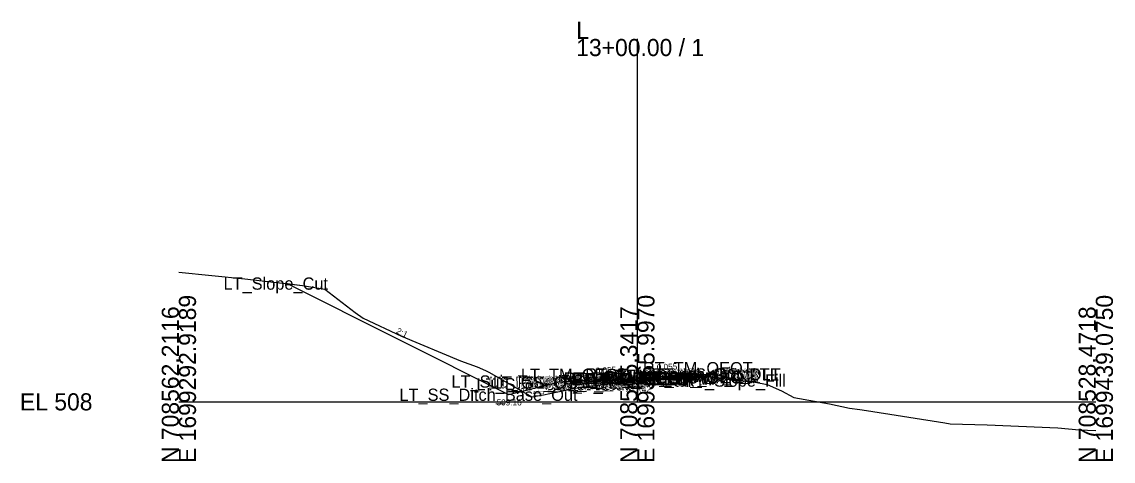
# Model space of a CAD drawing. Extents: x -63 to 1153, y -24 to 9522.
# Drawn here: x -25.7 to 152.8, y 2990.3 to 3062.1 of the extents above; entities that cross this region are included whole.
import ezdxf

# ---------------------------------------------------------------- set-up
doc = ezdxf.new("R2010")
doc.units = 0
for name, color, linetype in [('Default', 7, 'Continuous'), ('Exist Cross Section Cell', 7, 'Continuous'), ('Exist XS Center Line Elevation Label', 7, 'Continuous'), ('Exist XS Ground Line', 7, 'Continuous'), ('Prop CMT DNC', 7, 'Continuous'), ('Prop CMT Pvmt Course 1', 7, 'Continuous'), ('Prop CMT Pvmt Course 2', 7, 'Continuous'), ('Prop CMT Pvmt Surface', 7, 'Continuous'), ('Prop CMT Pvmt Surface Overlay', 7, 'Continuous'), ('Prop CMT Pvmt Surface Shoulder', 7, 'Continuous'), ('Prop CMT Shld Paved Course 1', 7, 'Continuous'), ('Prop CMT Shld Paved Course 2', 7, 'Continuous'), ('Prop CMT Slope Grass', 7, 'Continuous'), ('Prop CMT Subgrade Earthwork', 7, 'Continuous'), ('Prop XS Ditch Standard Text', 7, 'Continuous'), ('Prop XS Earthwork Shape', 7, 'Continuous'), ('Prop XS EOT Tick Mark', 7, 'Continuous'), ('Prop XS SE Text', 7, 'Continuous'), ('Prop XS Side Slope Text', 7, 'Continuous')]:
    doc.layers.add(name, color=color, linetype=linetype)

msp = doc.modelspace()

# ---------------------------------------------------------------- linework, layer by layer
at = {"layer": 'Exist Cross Section Cell'}
for p, q in [((75, 3000), (75, 3059.31)), ((0, 3000), (75, 3000)), ((75, 3000), (150, 3000))]:
    msp.add_line(p, q, dxfattribs=at)
at = {"layer": 'Exist XS Ground Line'}
msp.add_lwpolyline([(0, 3021.18), (10.8, 3020.12), (20.2, 3019.04), (23.85, 3018.4), (28.85, 3014.6), (30.17, 3013.65), (36.4, 3010.71), (46.07, 3006.73), (48.77, 3005.72), (50.17, 3005.1), (50.79, 3004.78), (57.73, 3000.83), (59.65, 3001.15), (60.69, 3001.36), (64.88, 3002.23), (65.63, 3002.38), (74.46, 3003.36), (75, 3003.42), (75.52, 3003.48), (84.57, 3004.15), (85.48, 3004.23), (86.59, 3004.13), (88.81, 3003.84), (94.26, 3003.22), (96.26, 3002.84), (98.58, 3001.79), (100.59, 3000.72), (106.43, 2999.65), (109.71, 2998.96), (111.4, 2998.73), (112.49, 2998.6), (125.28, 2996.55), (126.2, 2996.42), (132.2, 2996.22), (143.78, 2995.76), (147.25, 2995.45), (150, 2995.32)], dxfattribs=at)
at = {"layer": 'Prop CMT Pvmt Course 1'}
for points in [[(75, 3003.95), (65, 3003.4)], [(65, 3003.15), (75, 3003.7)], [(65, 3003.4), (65, 3003.15)], [(75, 3003.95), (85, 3004.5)], [(85, 3004.25), (75, 3003.7)], [(75, 3003.82), (75, 3003.95)], [(75, 3003.82), (75, 3003.95)], [(75, 3003.7), (75, 3003.82), (75, 3003.82)], [(75, 3003.7), (75, 3003.82), (75, 3003.82)], [(85, 3004.5), (85, 3004.25)]]:
    msp.add_lwpolyline(points, dxfattribs=at)
at = {"layer": 'Prop CMT Pvmt Course 2'}
for points in [[(75, 3003.7), (65, 3003.15)], [(65, 3002.9), (75, 3003.45)], [(65, 3003.15), (65, 3002.9)], [(75, 3003.7), (85, 3004.25)], [(85, 3004), (75, 3003.45)], [(75, 3003.45), (75, 3003.7)], [(75, 3003.45), (75, 3003.7)], [(85, 3004.25), (85, 3004)]]:
    msp.add_lwpolyline(points, dxfattribs=at)
at = {"layer": 'Prop CMT Pvmt Surface'}
for points in [[(75, 3003.95), (65, 3003.4)], [(75, 3003.95), (85, 3004.5)]]:
    msp.add_lwpolyline(points, dxfattribs=at)
at = {"layer": 'Prop CMT Pvmt Surface Overlay'}
for points in [[(75, 3003.95), (65, 3003.4)], [(75, 3003.95), (85, 3004.5)]]:
    msp.add_lwpolyline(points, dxfattribs=at)
at = {"layer": 'Prop CMT Pvmt Surface Shoulder'}
for points in [[(65, 3003.4), (64.99, 3003.4)], [(85, 3004.5), (85.01, 3004.5)]]:
    msp.add_lwpolyline(points, dxfattribs=at)
at = {"layer": 'Prop CMT Shld Paved Course 1'}
for points in [[(65, 3003.4), (64.99, 3003.4), (64.73, 3003.13)], [(64.73, 3003.13), (65, 3003.15)], [(65, 3003.15), (65, 3003.4)], [(85, 3004.5), (85.01, 3004.5), (85.25, 3004.26)], [(85, 3004.25), (85, 3004.5)], [(85.25, 3004.26), (85, 3004.25)]]:
    msp.add_lwpolyline(points, dxfattribs=at)
at = {"layer": 'Prop CMT Shld Paved Course 2'}
for points in [[(64.73, 3003.13), (64.46, 3002.87)], [(65, 3003.15), (64.73, 3003.13)], [(64.73, 3003.13), (64.73, 3003.13)], [(65, 3002.9), (65, 3003.15)], [(85, 3004.25), (85.25, 3004.26)], [(85, 3004), (85, 3004.25)], [(85.48, 3004.03), (85, 3004)], [(85.25, 3004.26), (85.25, 3004.26)], [(85.25, 3004.26), (85.48, 3004.03)], [(64.46, 3002.87), (65, 3002.9)]]:
    msp.add_lwpolyline(points, dxfattribs=at)
at = {"layer": 'Prop CMT Slope Grass'}
for points in [[(62, 3003.16), (54, 3001.16), (17.66, 3019.33)], [(64.99, 3003.4), (62, 3003.16)], [(85.01, 3004.5), (88, 3004.48)], [(88, 3004.48), (92.02, 3003.48)]]:
    msp.add_lwpolyline(points, dxfattribs=at)
at = {"layer": 'Prop CMT Subgrade Earthwork'}
for points in [[(64.46, 3002.87), (64.01, 3003.32)], [(75, 3003.45), (65, 3002.9)], [(75, 3003.45), (85, 3004)], [(85, 3004), (85.48, 3004.03)], [(85.48, 3004.03), (85.95, 3004.49)], [(65, 3002.9), (64.46, 3002.87)]]:
    msp.add_lwpolyline(points, dxfattribs=at)
at = {"layer": 'Prop XS Earthwork Shape'}
for points in [[(50.17, 3005.1), (50.79, 3004.78), (56.19, 3001.71), (54, 3001.16), (17.66, 3019.33), (20.2, 3019.04), (23.85, 3018.4), (28.85, 3014.6), (30.17, 3013.65), (36.4, 3010.71), (46.07, 3006.73), (48.77, 3005.72)], [(57.73, 3000.83), (59.65, 3001.15), (60.69, 3001.36), (64.88, 3002.23), (65.63, 3002.38), (74.46, 3003.36), (75, 3003.42), (75.49, 3003.48), (75, 3003.45), (65, 3002.9), (64.46, 3002.87), (64.01, 3003.32), (62, 3003.16), (56.19, 3001.71)], [(85.48, 3004.03), (85.67, 3004.21), (85.48, 3004.23), (84.57, 3004.15), (75.52, 3003.48), (75.49, 3003.48), (85, 3004)], [(85.95, 3004.49), (88, 3004.48), (92.02, 3003.48), (88.81, 3003.84), (86.59, 3004.13), (85.67, 3004.21)]]:
    msp.add_lwpolyline(points, close=True, dxfattribs=at)
at = {"layer": 'Prop XS EOT Tick Mark'}
for points in [[(85, 3004.5), (85, 3005.5)], [(65, 3003.4), (65, 3004.4)]]:
    msp.add_lwpolyline(points, dxfattribs=at)

# ---------------------------------------------------------------- texts
at = {"layer": 'Default'}
msp.add_text('-', height=0.0001, dxfattribs=at).set_placement((0, 3000))
at = {"layer": 'Exist Cross Section Cell'}
for s, p in [('L', (65, 3059.31)), ('13+00.00 / 1', (65, 3056.51)), ('EL 508', (-26, 2998.6))]:
    msp.add_text(s, height=2.8, dxfattribs=at).set_placement(p)
for s, p in [('E 1699292.9189', (2.8, 2990)), ('E 1699365.9970', (77.8, 2990)), ('E 1699439.0750', (152.8, 2990)), ('N 708562.2116', (0, 2990)), ('N 708545.3417', (75, 2990)), ('N 708528.4718', (150, 2990))]:
    msp.add_text(s, height=2.8, rotation=90, dxfattribs=at).set_placement(p)
at = {"layer": 'Exist XS Center Line Elevation Label'}
msp.add_text('511.42', height=1, dxfattribs=at).set_placement((73.13, 3001.56))
at = {"layer": 'Prop CMT DNC'}
for s, p in [('LT_Slope_Cut', (7.3, 3018.33)), ('RT_TM_OEOT', (75.9, 3004.5)), ('LT_TM_OEOT', (55.94, 3003.4)), ('RT_PV1_OEEOP_W', (62.94, 3002.82)), ('LT_PV1_OEEOP_W', (62.98, 3002.82)), ('RT_PV2_OEEOP', (64.26, 3002.7)), ('LT_PV2_OEEOP', (64.31, 3002.7)), ('RT_Sub_Trench_Out_DLT', (66.47, 3003.49)), ('PV1_PGL_W', (67.58, 3002.82)), ('PV1_PGL', (69.47, 3002.95)), ('RT_Sub_Trench_Out', (69.64, 3003.03)), ('RT_PS2_Shelf_Out', (71.18, 3003.26)), ('RT_Sub_OEOT', (75.03, 3003)), ('RT_PV2_OEOT', (75.13, 3003.25)), ('RT_PS2_OEOP', (75.44, 3003.26)), ('RT_PV1_OEOT', (75.69, 3003.5)), ('RT_PS1_OEOP', (75.77, 3003.5)), ('RT_GS_OS_CTL', (77.32, 3003.48)), ('LT_Sub_Trench_Out_DLT', (44.58, 3002.32)), ('LT_Sub_Trench_Out', (48.67, 3001.87)), ('LT_PS2_Shelf_Out', (50.71, 3002.13)), ('LT_GS_OS_CTL', (51.37, 3002.16)), ('LT_PS2_OEOP', (54.96, 3002.13)), ('LT_Sub_OEOT', (55.08, 3001.9)), ('LT_PV2_OEOT', (55.17, 3002.15)), ('LT_PV1_OEOT', (55.74, 3002.4)), ('LT_PS1_OEOP', (55.79, 3002.4)), ('RT_Sub_OEEOP', (64.17, 3002.45)), ('LT_Sub_OEEOP', (64.21, 3002.45)), ('RT_Slope_Fill', (82.5, 3002.48)), ('LT_SS_Ditch_Base_Out', (36.08, 3000.16))]:
    msp.add_text(s, height=2, dxfattribs=at).set_placement(p)
at = {"layer": 'Prop XS Ditch Standard Text'}
msp.add_text('509.16', height=1, dxfattribs=at).set_placement((51.98, 2999.41))
at = {"layer": 'Prop XS SE Text'}
for p in [(68.21, 3004.58), (78.21, 3005.13)]:
    msp.add_text('0.055', height=1, rotation=3.1481, dxfattribs=at).set_placement(p)
at = {"layer": 'Prop XS Side Slope Text'}
for s, rotation, p in [('2:1', 333.4349, (35.46, 3011.27)), ('4:1', 345.9638, (89.42, 3004.9)), ('4:1', 14.0362, (57.05, 3002.69))]:
    msp.add_text(s, height=1, rotation=rotation, dxfattribs=at).set_placement(p)

doc.saveas('drawing.dxf')
